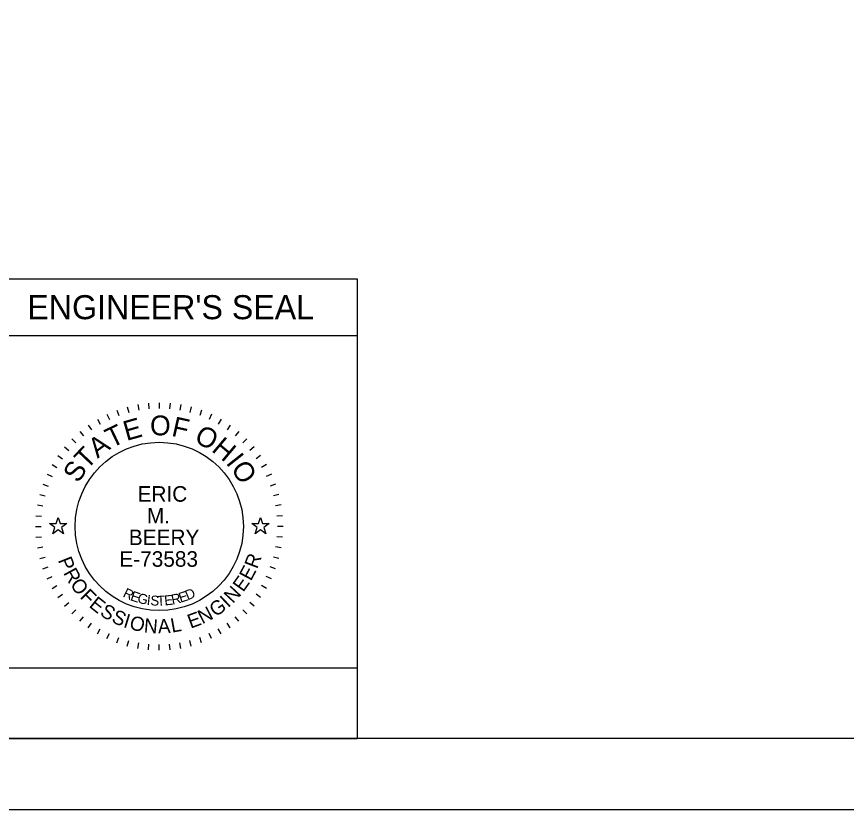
# Model space of a CAD drawing. Extents: x 0 to 34, y 0 to 22.
# Drawn here: x 22.27 to 28.13, y 0 to 5.6 of the extents above; entities that cross this region are included whole.
import ezdxf

# ---------------------------------------------------------------- set-up
doc = ezdxf.new("R2010")
doc.units = 0
for name, color, linetype in [('SH_Border', 7, 'Continuous'), ('SH_Cut_Line', 7, 'Continuous'), ('SH_Data', 7, 'Continuous'), ('SH_Seal', 7, 'Continuous')]:
    doc.layers.add(name, color=color, linetype=linetype)

msp = doc.modelspace()

# ---------------------------------------------------------------- linework, layer by layer
at = {"layer": 'SH_Border'}
msp.add_lwpolyline([(1.5, 21.5), (33.5, 21.5), (33.5, 0.5), (1.5, 0.5)], close=True, dxfattribs=at)
at = {"layer": 'SH_Cut_Line'}
msp.add_lwpolyline([(0, 0), (34, 0), (34, 22), (0, 22)], close=True, dxfattribs=at)
at = {"layer": 'SH_Data'}
for p, q in [((21.875, 3.75), (24.675, 3.75)), ((24.675, 3.75), (24.675, 0.5)), ((21.875, 3.35), (24.675, 3.35)), ((21.875, 0.5), (24.675, 0.5))]:
    msp.add_line(p, q, dxfattribs=at)
msp.add_lwpolyline([(21.875, 0.5), (21.875, 1), (24.675, 1), (24.675, 0.5)], close=True, dxfattribs=at)
at = {"layer": 'SH_Seal'}
for p, q in [((23.275, 2.875), (23.275, 2.835)), ((22.9757, 2.8222), (22.9894, 2.7846)), ((23.0485, 2.8452), (23.0589, 2.8065)), ((23.1231, 2.8617), (23.13, 2.8223)), ((23.1987, 2.8717), (23.2022, 2.8318)), ((23.3513, 2.8717), (23.3478, 2.8318)), ((23.4269, 2.8617), (23.42, 2.8223)), ((23.5015, 2.8452), (23.4911, 2.8065)), ((23.5743, 2.8222), (23.5606, 2.7846)), ((22.8375, 2.7578), (22.8575, 2.7231)), ((22.9052, 2.793), (22.9221, 2.7568)), ((23.6448, 2.793), (23.6279, 2.7568)), ((23.7125, 2.7578), (23.6925, 2.7231)), ((22.7731, 2.7168), (22.7961, 2.684)), ((23.7769, 2.7168), (23.7539, 2.684)), ((22.7126, 2.6703), (22.7383, 2.6396)), ((23.8374, 2.6703), (23.8117, 2.6396)), ((22.6563, 2.6187), (22.6846, 2.5904)), ((23.8937, 2.6187), (23.8654, 2.5904)), ((22.6047, 2.5624), (22.6354, 2.5367)), ((23.9453, 2.5624), (23.9146, 2.5367)), ((22.5582, 2.5019), (22.591, 2.4789)), ((23.9918, 2.5019), (23.959, 2.4789)), ((22.5172, 2.4375), (22.5519, 2.4175)), ((24.0328, 2.4375), (23.9981, 2.4175)), ((22.482, 2.3698), (22.5182, 2.3529)), ((24.068, 2.3698), (24.0318, 2.3529)), ((22.4528, 2.2993), (22.4904, 2.2856)), ((24.0972, 2.2993), (24.0596, 2.2856)), ((22.4298, 2.2265), (22.4685, 2.2161)), ((24.1202, 2.2265), (24.0815, 2.2161)), ((22.4133, 2.1519), (22.4527, 2.145)), ((24.1367, 2.1519), (24.0973, 2.145)), ((22.4033, 2.0763), (22.4432, 2.0728)), ((24.1467, 2.0763), (24.1068, 2.0728)), ((22.4, 2), (22.44, 2)), ((24.15, 2), (24.11, 2)), ((22.4033, 1.9237), (22.4432, 1.9272)), ((24.1467, 1.9237), (24.1068, 1.9272)), ((22.4133, 1.8481), (22.4527, 1.855)), ((24.1367, 1.8481), (24.0973, 1.855)), ((22.4298, 1.7735), (22.4685, 1.7839)), ((24.1202, 1.7735), (24.0815, 1.7839)), ((22.4528, 1.7007), (22.4904, 1.7144)), ((24.0972, 1.7007), (24.0596, 1.7144)), ((22.482, 1.6302), (22.5182, 1.6471)), ((24.068, 1.6302), (24.0318, 1.6471)), ((22.5172, 1.5625), (22.5519, 1.5825)), ((24.0328, 1.5625), (23.9981, 1.5825)), ((22.5582, 1.4981), (22.591, 1.5211)), ((23.9918, 1.4981), (23.959, 1.5211)), ((22.6047, 1.4376), (22.6354, 1.4633)), ((22.6563, 1.3813), (22.6846, 1.4096)), ((23.8937, 1.3813), (23.8654, 1.4096)), ((23.9453, 1.4376), (23.9146, 1.4633)), ((22.7126, 1.3297), (22.7383, 1.3604)), ((23.8374, 1.3297), (23.8117, 1.3604)), ((22.7731, 1.2832), (22.7961, 1.316)), ((23.7769, 1.2832), (23.7539, 1.316)), ((22.8375, 1.2422), (22.8575, 1.2769)), ((22.9052, 1.207), (22.9221, 1.2432)), ((23.6448, 1.207), (23.6279, 1.2432)), ((23.7125, 1.2422), (23.6925, 1.2769)), ((22.9757, 1.1778), (22.9894, 1.2154)), ((23.0485, 1.1548), (23.0589, 1.1935)), ((23.1231, 1.1383), (23.13, 1.1777)), ((23.4269, 1.1383), (23.42, 1.1777)), ((23.5015, 1.1548), (23.4911, 1.1935)), ((23.5743, 1.1778), (23.5606, 1.2154)), ((23.1987, 1.1283), (23.2022, 1.1682)), ((23.275, 1.125), (23.275, 1.165)), ((23.3513, 1.1283), (23.3478, 1.1682))]:
    msp.add_line(p, q, dxfattribs=at)
for points in [[(22.4986, 2.02), (22.5455, 2.02), (22.56, 2.0645), (22.5745, 2.02), (22.6214, 2.02), (22.5835, 1.9924), (22.598, 1.9478), (22.56, 1.9754), (22.522, 1.9478), (22.5365, 1.9924)], [(23.9286, 2.02), (23.9755, 2.02), (23.99, 2.0645), (24.0045, 2.02), (24.0514, 2.02), (24.0135, 1.9924), (24.028, 1.9478), (23.99, 1.9754), (23.952, 1.9478), (23.9665, 1.9924)]]:
    msp.add_lwpolyline(points, close=True, dxfattribs=at)
msp.add_circle((23.275, 2), 0.595, dxfattribs=at)

# ---------------------------------------------------------------- texts
at = {"layer": 'SH_Data'}
msp.add_text("ENGINEER'S SEAL", height=0.17, dxfattribs=at).set_placement((22.3426, 3.465))
at = {"layer": 'SH_Seal'}
for s, height, rotation, p in [('E', 0.14, 15.75706, (23.0434, 2.6038)), ('O', 0.14, 359.78119, (23.2097, 2.6443)), ('F', 0.14, 347.43619, (23.3561, 2.6417)), ('T', 0.14, 25.71674, (22.9366, 2.5518)), ('O', 0.14, 332.25863, (23.5148, 2.6015)), ('A', 0.14, 36.47472, (22.8384, 2.4781)), ('H', 0.14, 319.91363, (23.6382, 2.5361)), ('T', 0.14, 46.4344, (22.7633, 2.3964)), ('I', 0.14, 308.36695, (23.7415, 2.4483)), ('S', 0.14, 57.19238, (22.7031, 2.3014)), ('O', 0.14, 303.14906, (23.7771, 2.4089)), ('P', 0.1, 291.49398, (22.5573, 1.7621)), ('R', 0.1, 69.23216, (23.9669, 1.6954)), ('R', 0.1, 298.73106, (22.594, 1.6717)), ('E', 0.1, 61.99508, (23.9226, 1.6098)), ('E', 0.1, 54.75801, (23.8683, 1.5314)), ('O', 0.1, 306.46664, (22.6405, 1.5883)), ('F', 0.1, 314.7068, (22.7093, 1.4983)), ('R', 0.07, 334.48695, (23.0125, 1.5051)), ('E', 0.07, 341.03996, (23.0656, 1.4801)), ('G', 0.07, 347.47515, (23.1164, 1.4618)), ('R', 0.07, 11.91844, (23.3675, 1.4474)), ('E', 0.07, 17.68363, (23.4248, 1.4602)), ('D', 0.07, 23.30524, (23.476, 1.477)), ('N', 0.1, 47.02243, (23.7952, 1.4508)), ('E', 0.1, 321.43929, (22.7728, 1.4348)), ('I', 0.07, 353.78581, (23.1841, 1.4468)), ('S', 0.07, 356.89262, (23.2108, 1.4429)), ('T', 0.07, 3.00609, (23.2607, 1.4387)), ('E', 0.07, 6.01169, (23.3139, 1.4412)), ('G', 0.1, 35.04687, (23.6731, 1.357)), ('I', 0.1, 43.28703, (23.7618, 1.4214)), ('S', 0.1, 328.67637, (22.8493, 1.3752)), ('N', 0.1, 27.31129, (23.5795, 1.3075)), ('S', 0.1, 335.91345, (22.9314, 1.3266)), ('I', 0.1, 343.15053, (23.0156, 1.2897)), ('O', 0.1, 346.88592, (23.0589, 1.2751)), ('N', 0.1, 355.12608, (23.1638, 1.2517)), ('L', 0.1, 10.09874, (23.3644, 1.249)), ('E', 0.1, 20.07421, (23.4962, 1.277)), ('A', 0.1, 2.86166, (23.2673, 1.2437))]:
    msp.add_text(s, height=height, rotation=rotation, dxfattribs=at).set_placement(p)
for s, p in [('ERIC', (23.1215, 2.1749)), ('M.', (23.1876, 2.0216)), ('BEERY', (23.0598, 1.8684)), ('E-73583', (22.9927, 1.7151))]:
    msp.add_text(s, height=0.11, dxfattribs=at).set_placement(p)

doc.saveas('drawing.dxf')
